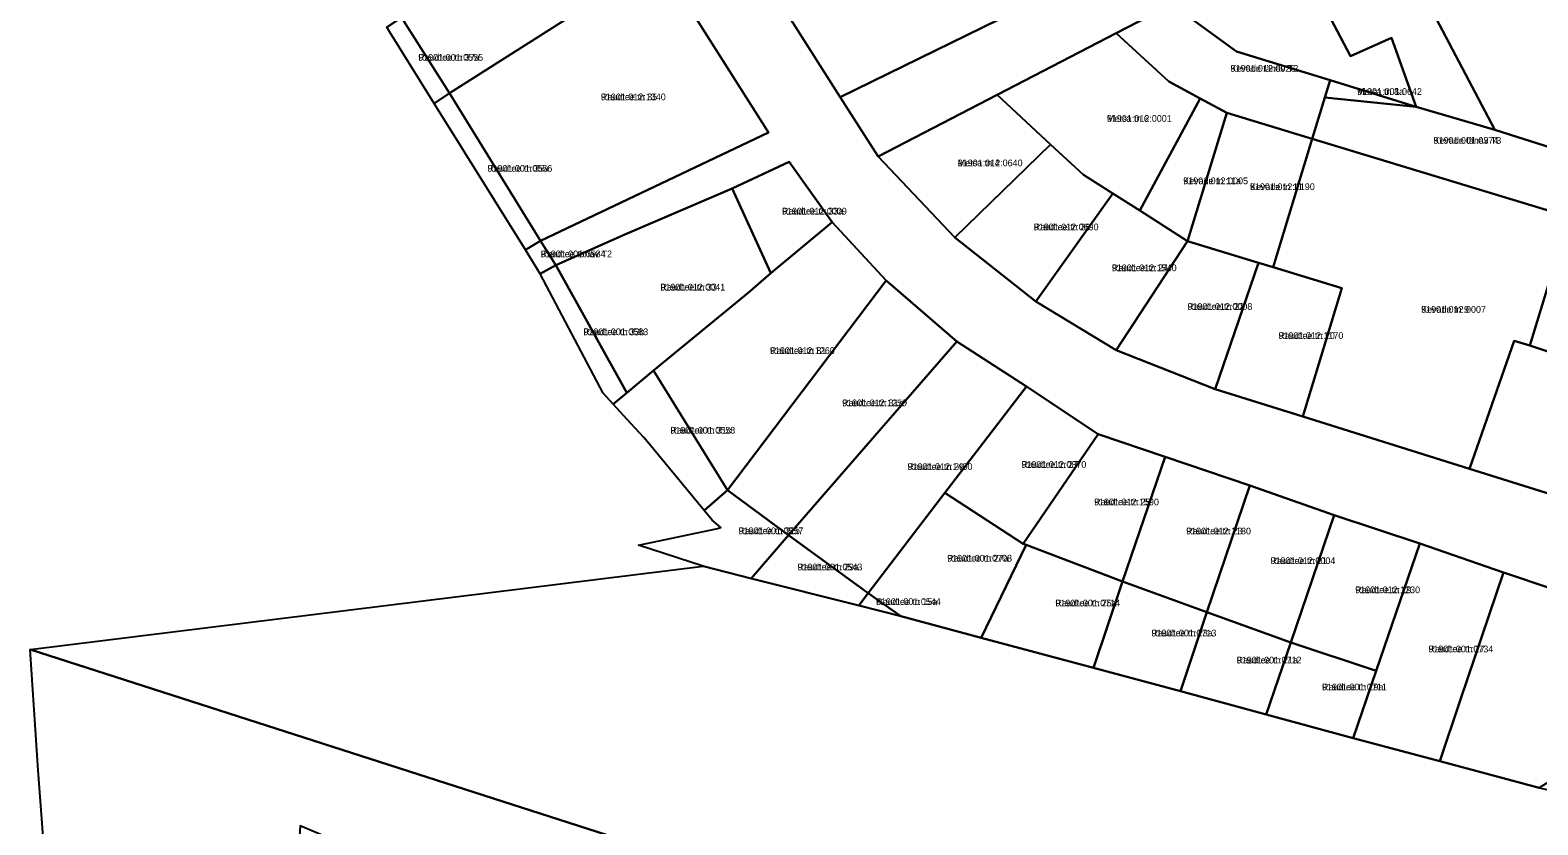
# Model space of a CAD drawing. Extents: x 675810 to 681273, y 6411190 to 6417565.
# Drawn here: x 678294 to 678631.2, y 6413542.7 to 6413720.5 of the extents above; entities that cross this region are included whole.
import ezdxf

# ---------------------------------------------------------------- set-up
doc = ezdxf.new("R2010")
doc.units = 0
for name, color, linetype in [('L_AADRESS', 7, 'Continuous'), ('PIIR', 7, 'Continuous'), ('TUNNUS', 7, 'Continuous')]:
    doc.layers.add(name, color=color, linetype=linetype)

msp = doc.modelspace()

# ---------------------------------------------------------------- linework, layer by layer
at = {"layer": 'PIIR'}
for points in [[(678634.29, 6413786.17), (678640.77, 6413773.75), (678614.14, 6413759.93), (678594.62, 6413749.78), (678576.03, 6413739.92), (678549.31, 6413726.23), (678536.93, 6413719.83), (678510.3, 6413706), (678483.68, 6413692.21), (678475.14, 6413705.51), (678524.84, 6413729.88), (678529.34, 6413732.11), (678541.98, 6413738.26), (678558.84, 6413747.01), (678575.25, 6413755.53), (678590.79, 6413763.59), (678607.37, 6413772.19)], [(678500.14, 6413777.83), (678526.12, 6413737.17), (678521.64, 6413734.97), (678524.84, 6413729.88), (678475.14, 6413705.51), (678449.57, 6413745.82), (678474.92, 6413762.05)], [(678434.67, 6413736.25), (678387.78, 6413706.37), (678377.05, 6413723.35), (678423.93, 6413752.97)], [(678589.34, 6413714.68), (678576.03, 6413739.92), (678594.62, 6413749.78), (678607.75, 6413724.49), (678621.57, 6413698.17), (678604.03, 6413703.32), (678598.52, 6413718.81)], [(678576.03, 6413739.92), (678589.34, 6413714.68), (678598.52, 6413718.81), (678604.03, 6413703.32), (678584.77, 6413709.31), (678563.8, 6413715.72), (678549.31, 6413726.23)], [(678434.67, 6413736.25), (678459.09, 6413697.62), (678408.15, 6413673.4), (678387.78, 6413706.37)], [(678636.17, 6413693.6), (678621.57, 6413698.17), (678607.75, 6413724.49), (678625.5, 6413733.71), (678628.37, 6413723.73), (678656.69, 6413735.21), (678665.33, 6413711.42)], [(678549.31, 6413726.23), (678563.8, 6413715.72), (678584.77, 6413709.31), (678583.58, 6413705.42), (678580.76, 6413696.15), (678561.63, 6413701.98), (678555.69, 6413705.21), (678548.71, 6413709), (678536.93, 6413719.83)], [(678384.37, 6413704.1), (678378.59, 6413713.37), (678374.42, 6413720.08), (678373.78, 6413721.16), (678377.05, 6413723.35), (678387.78, 6413706.37)], [(678536.93, 6413719.83), (678548.71, 6413709), (678555.69, 6413705.21), (678542.16, 6413680.14), (678536.14, 6413683.97), (678529.58, 6413688.15), (678522.23, 6413694.94), (678510.3, 6413706)], [(678604.03, 6413703.32), (678621.57, 6413698.17), (678636.17, 6413693.6), (678665.33, 6413711.42), (678669.76, 6413699.16), (678638.19, 6413678.73), (678580.76, 6413696.15), (678583.58, 6413705.42)], [(678584.77, 6413709.31), (678604.03, 6413703.32), (678583.58, 6413705.42)], [(678384.37, 6413704.1), (678387.78, 6413706.37), (678408.15, 6413673.4), (678404.79, 6413671.33)], [(678500.78, 6413674.1), (678483.68, 6413692.21), (678510.3, 6413706), (678522.23, 6413694.94)], [(678555.69, 6413705.21), (678561.63, 6413701.98), (678552.88, 6413673.28), (678542.16, 6413680.14)], [(678580.76, 6413696.15), (678572.02, 6413667.45), (678568.77, 6413668.44), (678552.88, 6413673.28), (678561.63, 6413701.98)], [(678629.4, 6413649.98), (678638.19, 6413678.73), (678669.76, 6413699.16), (678684.76, 6413656.15), (678644.66, 6413644.91)], [(678580.76, 6413696.15), (678638.19, 6413678.73), (678629.4, 6413649.98), (678625.89, 6413651.03), (678615.95, 6413622.4), (678578.67, 6413634.05), (678587.41, 6413662.75), (678572.02, 6413667.45)], [(678518.96, 6413659.79), (678500.78, 6413674.1), (678522.23, 6413694.94), (678529.58, 6413688.15), (678536.14, 6413683.97)], [(678463.77, 6413691.02), (678473.34, 6413677.54), (678459.63, 6413666.15), (678450.96, 6413685.11)], [(678450.96, 6413685.11), (678459.63, 6413666.15), (678454.59, 6413661.77), (678433.42, 6413644.38), (678427.43, 6413639.41), (678411.58, 6413667.91), (678427, 6413674.79)], [(678518.96, 6413659.79), (678536.14, 6413683.97), (678542.16, 6413680.14), (678552.88, 6413673.28), (678536.92, 6413648.9)], [(678485.47, 6413664.49), (678449.95, 6413617.64), (678433.42, 6413644.38), (678454.59, 6413661.77), (678459.63, 6413666.15), (678473.34, 6413677.54)], [(678408.15, 6413673.4), (678411.58, 6413667.91), (678408.01, 6413665.96), (678404.79, 6413671.33)], [(678552.88, 6413673.28), (678568.77, 6413668.44), (678559.01, 6413640.2), (678536.92, 6413648.9)], [(678572.02, 6413667.45), (678587.41, 6413662.75), (678578.67, 6413634.05), (678559.01, 6413640.2), (678568.77, 6413668.44)], [(678422.15, 6413639.32), (678408.01, 6413665.96), (678411.58, 6413667.91), (678427.43, 6413639.41), (678424.41, 6413636.83)], [(678501.23, 6413650.84), (678463.63, 6413607.52), (678449.95, 6413617.64), (678485.47, 6413664.49)], [(678685.97, 6413645.86), (678665.74, 6413606.8), (678615.95, 6413622.4), (678625.89, 6413651.03), (678629.4, 6413649.98), (678644.66, 6413644.91), (678684.76, 6413656.15)], [(678516.83, 6413640.76), (678498.59, 6413616.99), (678481.42, 6413594.57), (678463.63, 6413607.52), (678501.23, 6413650.84)], [(678432.06, 6413628.42), (678431.2, 6413629.36), (678428.33, 6413632.52), (678424.41, 6413636.83), (678427.43, 6413639.41), (678433.42, 6413644.38), (678449.95, 6413617.64), (678444.76, 6413613.04)], [(678498.59, 6413616.99), (678516.83, 6413640.76), (678532.84, 6413630.15), (678516.11, 6413605.61)], [(678547.82, 6413625.04), (678538.33, 6413597.15), (678516.78, 6413605.38), (678516.11, 6413605.61), (678532.84, 6413630.15)], [(678566.77, 6413618.67), (678557.2, 6413590.28), (678538.33, 6413597.15), (678547.82, 6413625.04)], [(678455.27, 6413597.88), (678444.52, 6413600.6), (678430.04, 6413605.33), (678447.39, 6413608.99), (678448.46, 6413609.22), (678446.53, 6413610.89), (678444.76, 6413613.04), (678449.95, 6413617.64), (678463.63, 6413607.52)], [(678566.77, 6413618.67), (678585.63, 6413611.98), (678575.93, 6413583.5), (678557.2, 6413590.28)], [(678481.42, 6413594.57), (678498.59, 6413616.99), (678516.11, 6413605.61), (678516.78, 6413605.38), (678506.69, 6413584.56), (678488.71, 6413589.4)], [(678604.81, 6413605.67), (678595.04, 6413577.16), (678575.93, 6413583.5), (678585.63, 6413611.98)], [(678455.27, 6413597.88), (678463.63, 6413607.52), (678481.42, 6413594.57), (678479.34, 6413591.8)], [(678506.69, 6413584.56), (678516.78, 6413605.38), (678538.33, 6413597.15), (678531.85, 6413577.83)], [(678589.92, 6413562.16), (678595.04, 6413577.16), (678604.81, 6413605.67), (678623.57, 6413599.18), (678613.91, 6413570.76), (678609.29, 6413557.01)], [(678613.91, 6413570.76), (678623.57, 6413599.18), (678656.18, 6413588.23), (678639.57, 6413556.01), (678631.5, 6413551.06), (678609.29, 6413557.01)], [(678481.42, 6413594.57), (678488.71, 6413589.4), (678479.34, 6413591.8)], [(678531.85, 6413577.83), (678538.33, 6413597.15), (678557.2, 6413590.28), (678551.27, 6413572.63)], [(678551.27, 6413572.63), (678557.2, 6413590.28), (678575.93, 6413583.5), (678570.48, 6413567.4)], [(678295.76, 6413554.98), (678293.96, 6413581.95), (678477.82, 6413522.85), (678458.5, 6413494.01), (678446.21, 6413498.66), (678451.25, 6413506.22), (678426.9, 6413514.62), (678389.61, 6413527.56), (678354.34, 6413542.49), (678352.55, 6413514.04), (678351.25, 6413513.9), (678354.14, 6413492.79), (678351.28, 6413483.5), (678325.9, 6413492.81), (678311.61, 6413482.73), (678306.63, 6413471.48), (678306.92, 6413457.06), (678308.78, 6413450.62), (678302.83, 6413437.81), (678298.35, 6413440.16), (678297.78, 6413528.19)], [(678570.48, 6413567.4), (678575.93, 6413583.5), (678595.04, 6413577.16), (678589.92, 6413562.16)]]:
    msp.add_lwpolyline(points, close=True, dxfattribs=at)
for points in [[(678449.57, 6413745.82), (678475.14, 6413705.51), (678483.68, 6413692.21), (678500.78, 6413674.1), (678518.96, 6413659.79), (678536.92, 6413648.9), (678559.01, 6413640.2), (678578.67, 6413634.05), (678615.95, 6413622.4), (678665.74, 6413606.8)], [(678656.18, 6413588.23), (678623.57, 6413599.18), (678604.81, 6413605.67), (678585.63, 6413611.98), (678566.77, 6413618.67), (678547.82, 6413625.04), (678532.84, 6413630.15), (678516.83, 6413640.76), (678501.23, 6413650.84), (678485.47, 6413664.49), (678473.34, 6413677.54), (678463.77, 6413691.02), (678450.96, 6413685.11), (678427, 6413674.79), (678411.58, 6413667.91), (678408.15, 6413673.4), (678459.09, 6413697.62), (678434.67, 6413736.25)], [(678477.82, 6413522.85), (678293.96, 6413581.95), (678444.52, 6413600.6), (678455.27, 6413597.88), (678479.34, 6413591.8), (678488.71, 6413589.4), (678506.69, 6413584.56), (678531.85, 6413577.83), (678551.27, 6413572.63), (678570.48, 6413567.4), (678589.92, 6413562.16), (678609.29, 6413557.01), (678631.5, 6413551.06), (678805.9, 6413512.49)]]:
    msp.add_lwpolyline(points, dxfattribs=at)

# ---------------------------------------------------------------- texts
at = {"layer": 'L_AADRESS'}
for s, p in [('Raudtee tn 37a', (678380.78, 6413713.65)), ('Kevade tänav T2', (678562.47, 6413711.19)), ('Raudtee tn 35', (678421.63, 6413704.82)), ('Metsa tn 8a', (678590.79, 6413706.02)), ('Metsa tn 6', (678534.83, 6413699.99)), ('Kevade tänav T3', (678607.88, 6413695.08)), ('Raudtee tn 35a', (678396.26, 6413688.83)), ('Metsa tn 4', (678501.46, 6413690.05)), ('Kevade tn 11a', (678551.89, 6413686.04)), ('Kevade tn 11', (678566.82, 6413684.72)), ('Raudtee tn 33a', (678462.15, 6413679.26)), ('Raudtee tn 26', (678518.46, 6413675.73)), ('Raudtee tänav T2', (678408.18, 6413669.7)), ('Raudtee tn 24', (678535.92, 6413666.58)), ('Raudtee tn 33', (678434.94, 6413662.26)), ('Raudtee tn 22', (678552.85, 6413657.93)), ('Kevade tn 9', (678605.11, 6413657.28)), ('Raudtee tn 33b', (678417.72, 6413652.27)), ('Raudtee tn 20', (678573.21, 6413651.42)), ('Raudtee tn 31', (678459.45, 6413648.08)), ('Raudtee tn 31a', (678475.59, 6413636.38)), ('Raudtee tn 31c', (678437.18, 6413630.26)), ('Raudtee tn 29', (678490.23, 6413622.12)), ('Raudtee tn 27', (678515.72, 6413622.59)), ('Raudtee tn 25', (678531.96, 6413614.22)), ('Raudtee tn 31b', (678452.43, 6413607.76)), ('Raudtee tn 23', (678552.55, 6413607.71)), ('Raudtee tn 29a', (678465.62, 6413599.66)), ('Raudtee tn 27a', (678499.1, 6413601.63)), ('Raudtee tn 21', (678571.42, 6413601.08)), ('Raudtee tn 19', (678590.37, 6413594.56)), ('Raudtee tn 15a', (678483.16, 6413591.92)), ('Raudtee tn 25a', (678523.29, 6413591.6)), ('Raudtee tn 23a', (678544.8, 6413584.89)), ('Raudtee tn 21a', (678563.85, 6413578.84)), ('Raudtee tn 17', (678606.75, 6413581.34)), ('Raudtee tn 19a', (678582.94, 6413572.83))]:
    msp.add_text(s, height=1.5, dxfattribs=at).set_placement(p)
at = {"layer": 'TUNNUS'}
for s, p in [('91901:001:0555', (678380.78, 6413713.65)), ('91901:012:0026', (678562.47, 6413711.19)), ('91901:012:1340', (678421.63, 6413704.82)), ('91901:001:0642', (678590.79, 6413706.02)), ('91901:012:0001', (678534.83, 6413699.99)), ('91901:001:0374', (678607.88, 6413695.08)), ('91901:001:0556', (678396.26, 6413688.83)), ('91901:012:0640', (678501.46, 6413690.05)), ('91901:012:0005', (678551.89, 6413686.04)), ('91901:012:1190', (678566.82, 6413684.72)), ('91901:012:0009', (678462.15, 6413679.26)), ('91901:012:0690', (678518.46, 6413675.73)), ('91901:001:0584', (678408.18, 6413669.7)), ('91901:012:1540', (678535.92, 6413666.58)), ('91901:012:0041', (678434.94, 6413662.26)), ('91901:012:0008', (678552.85, 6413657.93)), ('91901:012:0007', (678605.11, 6413657.28)), ('91901:001:0583', (678417.72, 6413652.27)), ('91901:012:1170', (678573.21, 6413651.42)), ('91901:012:1260', (678459.45, 6413648.08)), ('91901:012:1250', (678475.59, 6413636.38)), ('91901:001:0558', (678437.18, 6413630.26)), ('91901:012:1400', (678490.23, 6413622.12)), ('91901:012:0870', (678515.72, 6413622.59)), ('91901:012:1590', (678531.96, 6413614.22)), ('91901:001:0557', (678452.43, 6413607.76)), ('91901:012:1180', (678552.55, 6413607.71)), ('91901:001:0543', (678465.62, 6413599.66)), ('91901:001:0708', (678499.1, 6413601.63)), ('91901:012:0004', (678571.42, 6413601.08)), ('91901:012:1230', (678590.37, 6413594.56)), ('91901:001:0544', (678483.16, 6413591.92)), ('91901:001:0714', (678523.29, 6413591.6)), ('91901:001:0713', (678544.8, 6413584.89)), ('91901:001:0734', (678606.75, 6413581.34)), ('91901:001:0712', (678563.85, 6413578.84)), ('91901:001:0711', (678582.94, 6413572.83))]:
    msp.add_text(s, height=1.5, dxfattribs=at).set_placement(p)

doc.saveas('drawing.dxf')
